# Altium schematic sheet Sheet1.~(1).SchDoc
size A4
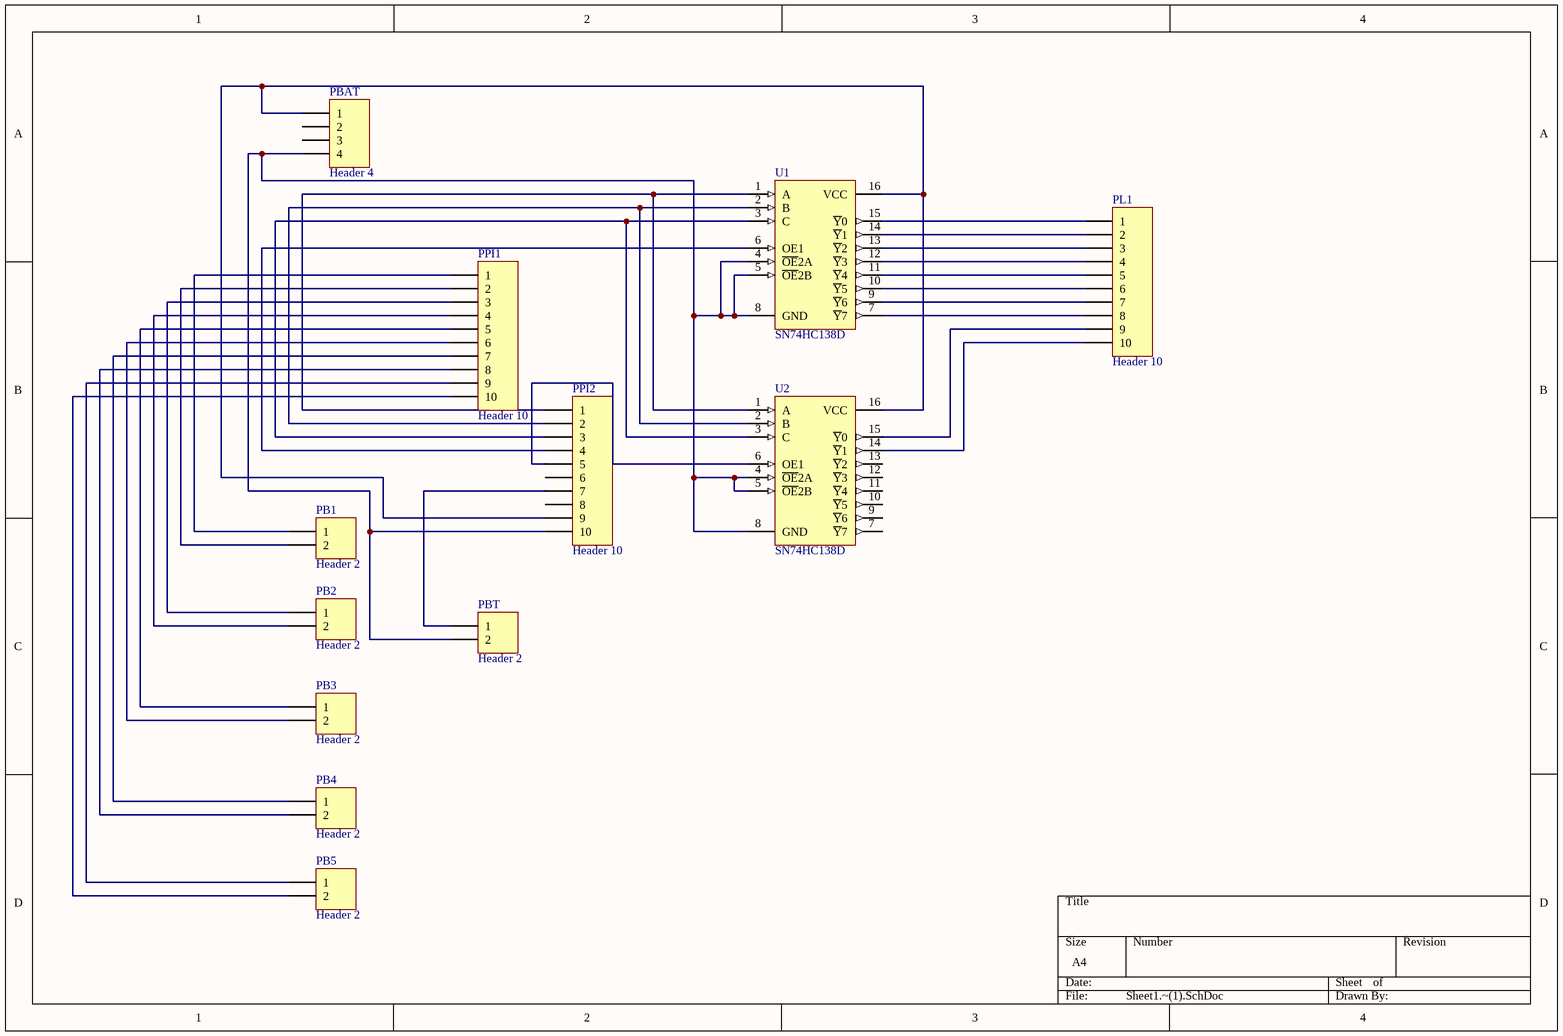
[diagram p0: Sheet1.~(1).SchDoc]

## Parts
PB1  Header 2  [HDR1X2]
PB2  Header 2  [HDR1X2]
PB3  Header 2  [HDR1X2]
PB4  Header 2  [HDR1X2]
PB5  Header 2  [HDR1X2]
PBAT  Header 4  [HDR1X4]
PBT  Header 2  [HDR1X2]
PL1  Header 10  [HDR1X10]
PPI1  Header 10  [HDR1X10]
PPI2  Header 10  [HDR1X10]
U1  SN74HC138D  [D016_N]
U2  SN74HC138D  [D016_N]

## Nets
NetPB1_1: PB1.1 PPI1.1
NetPB1_2: PB1.2 PPI1.2
NetPB2_1: PB2.1 PPI1.3
NetPB2_2: PB2.2 PPI1.4
NetPB3_1: PB3.1 PPI1.5
NetPB3_2: PB3.2 PPI1.6
NetPB4_1: PB4.1 PPI1.7
NetPB4_2: PB4.2 PPI1.8
NetPB5_1: PB5.1 PPI1.9
NetPB5_2: PB5.2 PPI1.10
NetPBAT_1: PBAT.1 PPI2.9 U1.16(VCC) U2.16(VCC)
NetPBAT_4: PBAT.4 PBT.2 PPI2.10 U1.4(~{OE}2A) U1.5(~{OE}2B) U1.8(GND) U2.4(~{OE}2A) U2.5(~{OE}2B) U2.8(GND)
NetPBT_1: PBT.1 PPI2.7
NetPL1_1: PL1.1 U1.15(~{Y}0)
NetPL1_2: PL1.2 U1.14(~{Y}1)
NetPL1_3: PL1.3 U1.13(~{Y}2)
NetPL1_4: PL1.4 U1.12(~{Y}3)
NetPL1_5: PL1.5 U1.11(~{Y}4)
NetPL1_6: PL1.6 U1.10(~{Y}5)
NetPL1_7: PL1.7 U1.9(~{Y}6)
NetPL1_8: PL1.8 U1.7(~{Y}7)
NetPL1_9: PL1.9 U2.15(~{Y}0)
NetPL1_10: PL1.10 U2.14(~{Y}1)
NetPPI2_1: PPI2.1 U1.1(A) U2.1(A)
NetPPI2_2: PPI2.2 U1.2(B) U2.2(B)
NetPPI2_3: PPI2.3 U1.3(C) U2.3(C)
NetPPI2_4: PPI2.4 U1.6(OE1)
NetPPI2_5: PPI2.5 U2.6(OE1)

Not connected (* = marked no-connect by the designer): PBAT 2 3; PPI2 6 8; U2 7(~{Y}7) 9(~{Y}6) 10(~{Y}5) 11(~{Y}4) 12(~{Y}3) 13(~{Y}2)

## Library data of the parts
PB1-PB5 PBT = Header 2: Header, 2-Pin
PBAT = Header 4: Header, 4-Pin
PL1 PPI1 PPI2 = Header 10: Header, 10-Pin
U1 U2 = SN74HC138D: 3-Line to 8-Line Decoder / Demultiplexer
